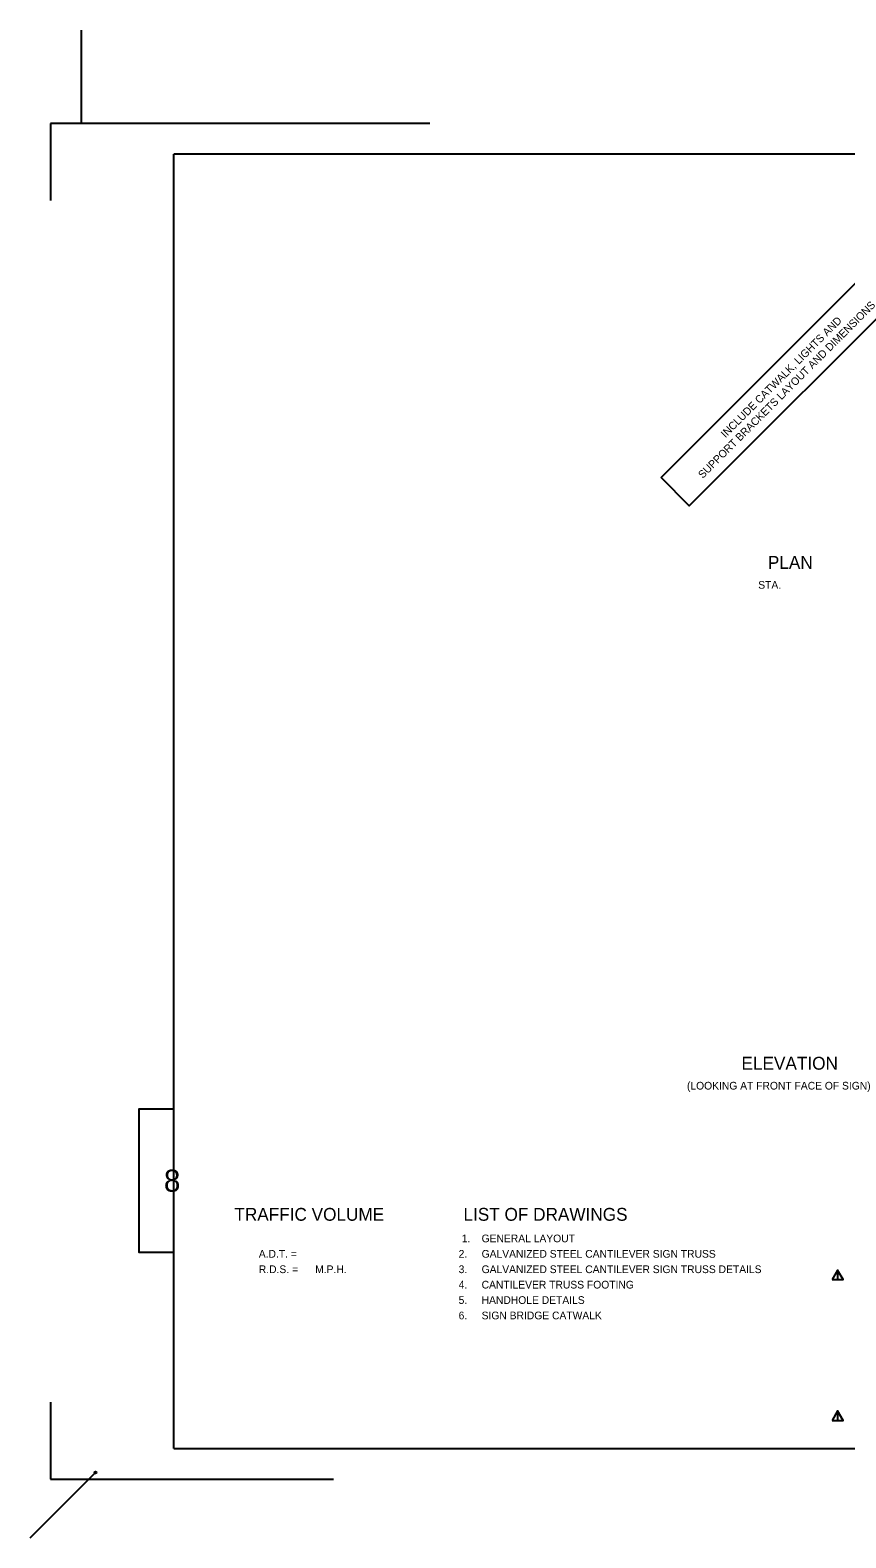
# Model space of a CAD drawing. Extents: x -21 to 58.5, y -15.2 to 40.8.
# Drawn here: x -21 to 8.7, y -14.3 to 40.8 of the extents above; entities that cross this region are included whole.
import ezdxf

# ---------------------------------------------------------------- set-up
doc = ezdxf.new("R2010")
doc.units = 0
for name, color, linetype in [('Level 1', 7, 'Continuous'), ('Level 11', 7, 'Continuous'), ('Level 2', 7, 'Continuous'), ('Level 49', 7, 'Continuous')]:
    doc.layers.add(name, color=color, linetype=linetype)

msp = doc.modelspace()

# ---------------------------------------------------------------- linework, layer by layer
at = {"layer": 'Level 1'}
for p, q in [((-6.452, 37.351), (-20.291, 37.351)), ((-20.291, 37.351), (-20.291, 34.533)), ((-15.791, -11.023), (-15.791, 36.226)), ((54.804, 36.226), (-15.791, 36.226)), ((-20.291, -9.33), (-20.291, -12.148)), ((-15.791, -11.023), (54.804, -11.023)), ((-20.291, -12.148), (-9.968, -12.148))]:
    msp.add_line(p, q, dxfattribs=at)
msp.add_lwpolyline([(-15.791, 1.363), (-17.068, 1.363), (-17.068, -3.86), (-15.791, -3.86)], close=True, dxfattribs=at)
at = {"layer": 'Level 11'}
msp.add_lwpolyline([(1.993, 24.418), (10.347, 32.772), (11.379, 31.74), (3.025, 23.386)], close=True, dxfattribs=at)
at = {"layer": 'Level 2'}
for p, q in [((-19.166, 37.351), (-19.166, 40.753)), ((-21.039, -14.289), (-18.652, -11.902))]:
    msp.add_line(p, q, dxfattribs=at)
for points in [[(8.239, -4.862), (8.64, -4.862), (8.439, -4.515)], [(8.439, -4.515), (8.439, -4.862), (8.64, -4.862)], [(8.239, -10.001), (8.64, -10.001), (8.439, -9.654)], [(8.439, -9.654), (8.439, -10.001), (8.64, -10.001)]]:
    msp.add_lwpolyline(points, close=True, dxfattribs=at)
at = {"layer": 'Level 49'}
msp.add_circle((-18.653, -11.902), 0.0342, dxfattribs=at)

# ---------------------------------------------------------------- texts
at = {"layer": 'Level 1'}
for s, height, p in [('PLAN', 0.4694, (5.894, 21.086)), ('ELEVATION', 0.4694, (4.93, 2.803)), ('8', 0.812, (-16.157, -1.655)), ('TRAFFIC VOLUME', 0.46874, (-13.582, -2.713)), ('LIST OF DRAWINGS', 0.46874, (-5.218, -2.713))]:
    msp.add_text(s, height=height, dxfattribs=at).set_placement(p)
at = {"layer": 'Level 11'}
for s, p in [('SUPPORT BRACKETS LAYOUT AND DIMENSIONS', (3.518, 24.367)), ('INCLUDE CATWALK, LIGHTS AND', (4.349, 25.855))]:
    msp.add_text(s, height=0.28125, rotation=45, dxfattribs=at).set_placement(p)
for s, height, p in [(' 5.  ', 0.2813, (-5.5, -5.749)), ('HANDHOLE DETAILS', 0.28125, (-4.556, -5.749)), (' 6.  ', 0.2813, (-5.5, -6.311)), ('SIGN BRIDGE CATWALK', 0.28125, (-4.556, -6.311))]:
    msp.add_text(s, height=height, dxfattribs=at).set_placement(p)
at = {"layer": 'Level 2'}
for s, height, p in [('STA.           ', 0.28125, (5.543, 20.361)), ('(LOOKING AT FRONT FACE OF SIGN)', 0.28125, (2.94, 2.077)), (' 1.  ', 0.2813, (-5.384, -3.499)), ('GENERAL LAYOUT', 0.28125, (-4.556, -3.499)), ('A.D.T. =           ', 0.28125, (-12.691, -4.061)), (' 2.  ', 0.2813, (-5.5, -4.061)), ('GALVANIZED STEEL CANTILEVER SIGN TRUSS', 0.28125, (-4.556, -4.061)), ('R.D.S. =      M.P.H.', 0.28125, (-12.691, -4.624)), (' 3.  ', 0.2813, (-5.5, -4.624)), ('GALVANIZED STEEL CANTILEVER SIGN TRUSS DETAILS', 0.28125, (-4.556, -4.624)), (' 4.  ', 0.2813, (-5.5, -5.186)), ('CANTILEVER TRUSS FOOTING', 0.28125, (-4.556, -5.186))]:
    msp.add_text(s, height=height, dxfattribs=at).set_placement(p)

doc.saveas('drawing.dxf')
